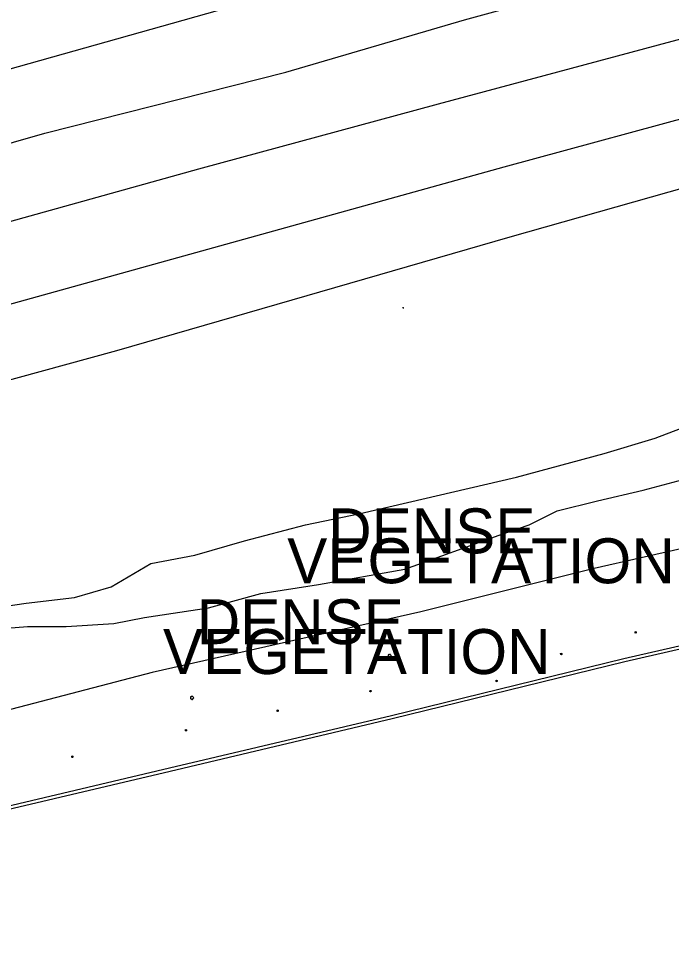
# Model space of a CAD drawing. Extents: x 2129547 to 2134906, y 657330 to 659734.
# Drawn here: x 2129941.3 to 2130043, y 657677.4 to 657821.5 of the extents above; entities that cross this region are included whole.
import ezdxf

# ---------------------------------------------------------------- set-up
doc = ezdxf.new("R2010")
doc.units = 0
for name, color, linetype in [('LT_X_Poles', 7, 'Continuous'), ('PM_X_Edge_Line', 7, 'Continuous'), ('PM_X_Lane_Line', 7, 'Continuous'), ('PV_X_Curb', 7, 'Continuous'), ('PV_X_EOP2', 7, 'Continuous'), ('PV_X_Parking_Lot', 7, 'Continuous'), ('PV_X_Shoulder', 7, 'Continuous'), ('SN_X_Public', 7, 'Continuous'), ('VG_X_Cells', 7, 'Continuous'), ('VG_X_Shrub_Line_Lt', 7, 'Continuous'), ('VG_X_Text', 7, 'Continuous'), ('VG_X_Tree_Line_Lt', 7, 'Continuous')]:
    doc.layers.add(name, color=color, linetype=linetype)

msp = doc.modelspace()

# ---------------------------------------------------------------- linework, layer by layer
at = {"layer": 'LT_X_Poles'}
msp.add_lwpolyline([(2130015.72, 657720.83), (2130015.64, 657720.53), (2130015.76, 657720.53)], dxfattribs=at)
msp.add_circle((2130015.68, 657720.68), 0.065, dxfattribs=at)
at = {"layer": 'PM_X_Edge_Line'}
for points in [[(2129782.31, 657770.56), (2129838.02, 657785.8), (2129918.94, 657807.73), (2130006.57, 657832.43), (2130060.5, 657847.21), (2130112.38, 657861.87), (2130166.66, 657876.43), (2130223.01, 657891.92), (2130282.32, 657908.07), (2130309.12, 657915.87), (2130347.7, 657926.43), (2130352.07, 657927.63), (2130411.57, 657944.11), (2130465.65, 657958.97), (2130518.8, 657973.53), (2130571.22, 657987.81), (2130618.14, 658000.71), (2130672.33, 658015.45), (2130724.27, 658029.78), (2130769.53, 658042.24), (2130813.51, 658054.13), (2130850.23, 658064.39), (2130880.11, 658072.6), (2130898.43, 658077.6)], [(2129781.33, 657733.06), (2129822.4, 657744.28), (2129902.75, 657766.7), (2130016.9, 657798.42), (2130084.9, 657816.89), (2130135.24, 657830.94), (2130189.26, 657846.05), (2130240.42, 657859.85), (2130282.16, 657871.36), (2130318.23, 657881.32), (2130332.01, 657885.16), (2130356.78, 657892.02), (2130375.64, 657897.24), (2130413.2, 657907.59), (2130448.12, 657917.07), (2130481.79, 657926.44), (2130514.96, 657935.23), (2130533.56, 657939.51)]]:
    msp.add_lwpolyline(points, dxfattribs=at)
at = {"layer": 'PM_X_Lane_Line'}
for points in [[(2129781.97, 657758.13), (2129790.58, 657760.5), (2129829.56, 657771.14), (2129869.63, 657781.89), (2129945.41, 657803.63), (2129982.9, 657813.16), (2130010.71, 657821.32), (2130048.97, 657831.8), (2130087.83, 657842.51), (2130137.07, 657856.3), (2130176.24, 657866.81), (2130213.39, 657877.02), (2130252.97, 657888.01), (2130290.12, 657898.33), (2130312.18, 657904.29), (2130329.72, 657909.17), (2130350.72, 657914.99), (2130369.2, 657920.1), (2130409.79, 657931.31), (2130447.91, 657941.44), (2130484.91, 657951.63), (2130526.03, 657962.85), (2130563.47, 657973.17)], [(2130557.28, 657959.92), (2130518.18, 657949.28), (2130479.22, 657938.42), (2130439.87, 657927.68), (2130400.48, 657916.61), (2130360.47, 657905.46), (2130353.72, 657903.61), (2130321.86, 657894.87), (2130315.15, 657893.02), (2130282.49, 657883.85), (2130241.71, 657872.68), (2130201.93, 657862), (2130163.85, 657851.39), (2130126, 657840.99), (2130086.64, 657830.21), (2130048.06, 657819.28), (2130006.64, 657808.18), (2129969.33, 657798.07), (2129930.34, 657787.23), (2129890.21, 657775.75), (2129850.72, 657764.54), (2129813.2, 657754.11), (2129781.62, 657745.43)]]:
    msp.add_lwpolyline(points, dxfattribs=at)
at = {"layer": 'PV_X_Curb'}
msp.add_lwpolyline([(2129884.57, 657679.15), (2129883.01, 657681.79), (2129889.43, 657687), (2129928.6, 657696.31), (2129964.8, 657704.85), (2129999.37, 657713.02), (2130035.56, 657721.89), (2130065.94, 657728.85), (2130090.35, 657734.59), (2130113.79, 657740.05), (2130134.12, 657744.97), (2130136.89, 657741.78)], dxfattribs=at)
at = {"layer": 'PV_X_EOP2'}
for points in [[(2129782.31, 657770.56), (2129838.02, 657785.8), (2129918.94, 657807.73), (2130006.57, 657832.43), (2130060.5, 657847.21), (2130112.38, 657861.87), (2130166.66, 657876.43), (2130223.01, 657891.92), (2130282.32, 657908.07), (2130309.12, 657915.87), (2130347.7, 657926.43), (2130352.07, 657927.63), (2130411.57, 657944.11), (2130465.65, 657958.97), (2130518.8, 657973.53), (2130571.22, 657987.81), (2130618.14, 658000.71), (2130672.33, 658015.45), (2130724.27, 658029.78), (2130769.53, 658042.24), (2130813.51, 658054.13), (2130850.23, 658064.39), (2130880.11, 658072.6), (2130898.43, 658077.6)], [(2129781.33, 657733.06), (2129822.4, 657744.28), (2129902.75, 657766.7), (2130016.9, 657798.42), (2130084.9, 657816.89), (2130135.24, 657830.94), (2130189.26, 657846.05), (2130240.42, 657859.85), (2130282.16, 657871.36), (2130318.23, 657881.32), (2130332.01, 657885.16), (2130356.78, 657892.02), (2130375.64, 657897.24), (2130413.2, 657907.59), (2130448.12, 657917.07), (2130481.79, 657926.44), (2130514.96, 657935.23), (2130533.56, 657939.51)]]:
    msp.add_lwpolyline(points, dxfattribs=at)
at = {"layer": 'PV_X_Parking_Lot'}
msp.add_lwpolyline([(2129885.07, 657679.28), (2129883.66, 657681.67), (2129889.66, 657686.54), (2129928.71, 657695.83), (2129964.91, 657704.36), (2129999.49, 657712.53), (2130035.68, 657721.4), (2130066.05, 657728.37), (2130090.47, 657734.1), (2130113.9, 657739.56), (2130133.94, 657744.42), (2130136.35, 657741.64)], dxfattribs=at)
at = {"layer": 'PV_X_Shoulder'}
msp.add_lwpolyline([(2129781.12, 657723.15), (2129791.26, 657725.96), (2129847.2, 657740.42), (2129910.54, 657757.22), (2129956.62, 657769.85), (2130017.82, 657787.52), (2130067.36, 657801.54), (2130112.53, 657814.1), (2130168.41, 657829.75), (2130217.23, 657843.2), (2130272.91, 657858.21), (2130320.81, 657871.55), (2130356.56, 657881.59), (2130359.33, 657882.35), (2130366.22, 657884.23)], dxfattribs=at)
at = {"layer": 'SN_X_Public'}
for p, q in [((2130001.2, 657776.39), (2130001.16, 657776.55)), ((2130001.18, 657776.47), (2130001.26, 657776.49))]:
    msp.add_line(p, q, dxfattribs=at)
at = {"layer": 'VG_X_Cells'}
for points in [[(2130037.38, 657726.04), (2130037.41, 657726.07), (2130037.43, 657726.02), (2130037.48, 657726.03), (2130037.47, 657725.98), (2130037.52, 657725.95), (2130037.47, 657725.91), (2130037.48, 657725.87), (2130037.45, 657725.87), (2130037.43, 657725.82), (2130037.41, 657725.86), (2130037.38, 657725.82), (2130037.35, 657725.86), (2130037.3, 657725.84), (2130037.31, 657725.89), (2130037.27, 657725.88), (2130037.3, 657725.92), (2130037.26, 657725.95), (2130037.29, 657725.97), (2130037.26, 657726.01), (2130037.31, 657726), (2130037.31, 657726.05), (2130037.35, 657726.02), (2130037.36, 657726.07), (2130037.38, 657726.04)], [(2130025.79, 657722.68), (2130025.82, 657722.72), (2130025.84, 657722.66), (2130025.9, 657722.67), (2130025.88, 657722.62), (2130025.93, 657722.59), (2130025.88, 657722.56), (2130025.9, 657722.51), (2130025.86, 657722.51), (2130025.84, 657722.47), (2130025.82, 657722.5), (2130025.79, 657722.46), (2130025.76, 657722.51), (2130025.71, 657722.48), (2130025.72, 657722.53), (2130025.68, 657722.53), (2130025.71, 657722.57), (2130025.67, 657722.6), (2130025.7, 657722.61), (2130025.67, 657722.65), (2130025.72, 657722.64), (2130025.72, 657722.7), (2130025.76, 657722.67), (2130025.77, 657722.72), (2130025.79, 657722.68)], [(2130015.72, 657718.49), (2130015.75, 657718.53), (2130015.77, 657718.47), (2130015.83, 657718.48), (2130015.81, 657718.43), (2130015.86, 657718.4), (2130015.81, 657718.37), (2130015.83, 657718.32), (2130015.79, 657718.32), (2130015.77, 657718.28), (2130015.75, 657718.31), (2130015.72, 657718.27), (2130015.7, 657718.32), (2130015.65, 657718.29), (2130015.66, 657718.34), (2130015.61, 657718.34), (2130015.64, 657718.38), (2130015.6, 657718.41), (2130015.64, 657718.42), (2130015.61, 657718.46), (2130015.65, 657718.45), (2130015.65, 657718.51), (2130015.69, 657718.48), (2130015.7, 657718.53), (2130015.72, 657718.49)], [(2129996.1, 657716.89), (2129996.13, 657716.92), (2129996.15, 657716.87), (2129996.2, 657716.88), (2129996.18, 657716.83), (2129996.23, 657716.8), (2129996.19, 657716.76), (2129996.2, 657716.72), (2129996.16, 657716.72), (2129996.15, 657716.68), (2129996.13, 657716.71), (2129996.09, 657716.67), (2129996.07, 657716.71), (2129996.02, 657716.69), (2129996.03, 657716.74), (2129995.99, 657716.74), (2129996.01, 657716.78), (2129995.97, 657716.8), (2129996.01, 657716.82), (2129995.98, 657716.86), (2129996.03, 657716.85), (2129996.03, 657716.9), (2129996.06, 657716.87), (2129996.07, 657716.92), (2129996.1, 657716.89)], [(2129981.63, 657713.83), (2129981.66, 657713.87), (2129981.68, 657713.81), (2129981.74, 657713.82), (2129981.72, 657713.77), (2129981.77, 657713.74), (2129981.72, 657713.71), (2129981.74, 657713.66), (2129981.7, 657713.66), (2129981.68, 657713.62), (2129981.66, 657713.65), (2129981.63, 657713.61), (2129981.61, 657713.66), (2129981.56, 657713.63), (2129981.57, 657713.68), (2129981.52, 657713.68), (2129981.55, 657713.72), (2129981.51, 657713.75), (2129981.55, 657713.76), (2129981.52, 657713.8), (2129981.56, 657713.79), (2129981.56, 657713.85), (2129981.6, 657713.82), (2129981.61, 657713.87), (2129981.63, 657713.83)], [(2129967.36, 657710.81), (2129967.39, 657710.85), (2129967.41, 657710.8), (2129967.47, 657710.8), (2129967.45, 657710.75), (2129967.5, 657710.72), (2129967.45, 657710.69), (2129967.47, 657710.64), (2129967.43, 657710.64), (2129967.41, 657710.6), (2129967.39, 657710.63), (2129967.36, 657710.59), (2129967.34, 657710.64), (2129967.28, 657710.62), (2129967.29, 657710.66), (2129967.25, 657710.66), (2129967.28, 657710.7), (2129967.24, 657710.73), (2129967.28, 657710.74), (2129967.25, 657710.78), (2129967.29, 657710.77), (2129967.29, 657710.83), (2129967.33, 657710.8), (2129967.34, 657710.85), (2129967.36, 657710.81)], [(2129949.66, 657706.67), (2129949.69, 657706.71), (2129949.71, 657706.66), (2129949.76, 657706.67), (2129949.75, 657706.62), (2129949.79, 657706.59), (2129949.75, 657706.55), (2129949.76, 657706.5), (2129949.73, 657706.51), (2129949.71, 657706.46), (2129949.69, 657706.5), (2129949.65, 657706.45), (2129949.63, 657706.5), (2129949.58, 657706.48), (2129949.59, 657706.52), (2129949.55, 657706.52), (2129949.57, 657706.56), (2129949.54, 657706.59), (2129949.57, 657706.6), (2129949.54, 657706.64), (2129949.59, 657706.64), (2129949.59, 657706.69), (2129949.63, 657706.66), (2129949.64, 657706.71), (2129949.66, 657706.67)]]:
    msp.add_lwpolyline(points, dxfattribs=at)
for centre, radius in [((2130037.38, 657725.95), 0.0115), ((2129999.06, 657722.3), 0.012), ((2130025.79, 657722.59), 0.0115), ((2130015.73, 657718.4), 0.0115), ((2129996.1, 657716.8), 0.0115), ((2129968.29, 657715.76), 0.012), ((2129981.64, 657713.74), 0.0115), ((2129967.36, 657710.72), 0.0115), ((2129949.66, 657706.58), 0.0115)]:
    msp.add_circle(centre, radius, dxfattribs=at)
for centre, radius, start, end in [((2129998.9, 657722.39), 0.0735, 39.0625, 279.5412), ((2129998.92, 657722.22), 0.0987, 96.1722, 320.5737), ((2129999.01, 657722.47), 0.0658, 354.0047, 205.9741), ((2129999.11, 657722.17), 0.114, 184.9476, 19.4572), ((2129999.15, 657722.44), 0.0776, 323.83, 165.0376), ((2129999.23, 657722.3), 0.0957, 259.1453, 101.4596), ((2129968.15, 657715.68), 0.0987, 96.1722, 320.5737), ((2129968.13, 657715.85), 0.0735, 39.0625, 279.5412), ((2129968.25, 657715.93), 0.0658, 354.0047, 205.9741), ((2129968.34, 657715.63), 0.114, 184.9476, 19.4572), ((2129968.39, 657715.9), 0.0776, 323.83, 165.0376), ((2129968.47, 657715.76), 0.0957, 259.1453, 101.4596)]:
    msp.add_arc(centre, radius, start, end, dxfattribs=at)
at = {"layer": 'VG_X_Shrub_Line_Lt'}
for points in [[(2130018.81, 657750.13), (2130032.49, 657753.79), (2130040.43, 657756.16), (2130048.7, 657759.33), (2130053.87, 657761.67), (2130057.28, 657763.33), (2130060.77, 657764.71), (2130064.36, 657765.7), (2130068.81, 657767.04), (2130070.22, 657767.4), (2130069.69, 657768.63), (2130069.28, 657770.01), (2130069.12, 657771.32), (2130069.49, 657772.54), (2130071.16, 657773.8), (2130095.59, 657781.36), (2130119.35, 657787.99), (2130145.24, 657794.52)], [(2129934.65, 657729.33), (2129942.48, 657730.49), (2129950, 657731.4), (2129955.7, 657733.03), (2129961.88, 657736.65), (2129968.73, 657737.99), (2129976.46, 657740.2), (2129985.96, 657742.69), (2129994.51, 657744.44), (2130018.81, 657750.13)]]:
    msp.add_lwpolyline(points, dxfattribs=at)
at = {"layer": 'VG_X_Tree_Line_Lt'}
for points in [[(2130137.84, 657742.02), (2130134.94, 657745), (2130134.06, 657745.81), (2130132.87, 657745.92), (2130129.58, 657745.09), (2130126.91, 657744.18), (2130123.36, 657743.33), (2130121.92, 657744.04), (2130120.17, 657746.03), (2130118.23, 657747.12), (2130115.03, 657748.07), (2130112.8, 657749.89), (2130111.38, 657751.77), (2130109, 657753.01), (2130105.12, 657752.48), (2130095.09, 657750.22), (2130073.23, 657745.53), (2130052.89, 657740.89), (2130030.94, 657735.91)], [(2129937.49, 657726.43), (2129942.68, 657726.85), (2129948.69, 657726.85), (2129956.11, 657727.31), (2129960.92, 657728.24), (2129970.86, 657729.79), (2129979.03, 657732.02), (2129988, 657733.39), (2130001.42, 657735.81), (2130016.15, 657741.08), (2130020.81, 657742.68), (2130025.16, 657744.85), (2130031.45, 657746.43), (2130038.56, 657748.08), (2130047.9, 657750.58)], [(2130030.94, 657735.91), (2130003.92, 657729.15), (2129962.08, 657719.69), (2129926.29, 657710.37), (2129889.05, 657698.98), (2129880.08, 657698.29), (2129877.39, 657695.71), (2129876.19, 657689.3), (2129875.73, 657686.81), (2129875.09, 657683.27), (2129874.5, 657681.88), (2129872.51, 657679.36), (2129871.15, 657677.36)]]:
    msp.add_lwpolyline(points, dxfattribs=at)

# ---------------------------------------------------------------- texts
at = {"layer": 'VG_X_Text'}
for s, p in [('DENSE', (2129989.51, 657738.25)), ('VEGETATION', (2129983.13, 657733.59)), ('DENSE', (2129969.05, 657724.11)), ('VEGETATION', (2129963.79, 657719.46))]:
    msp.add_text(s, height=7, dxfattribs=at).set_placement(p)

doc.saveas('drawing.dxf')
